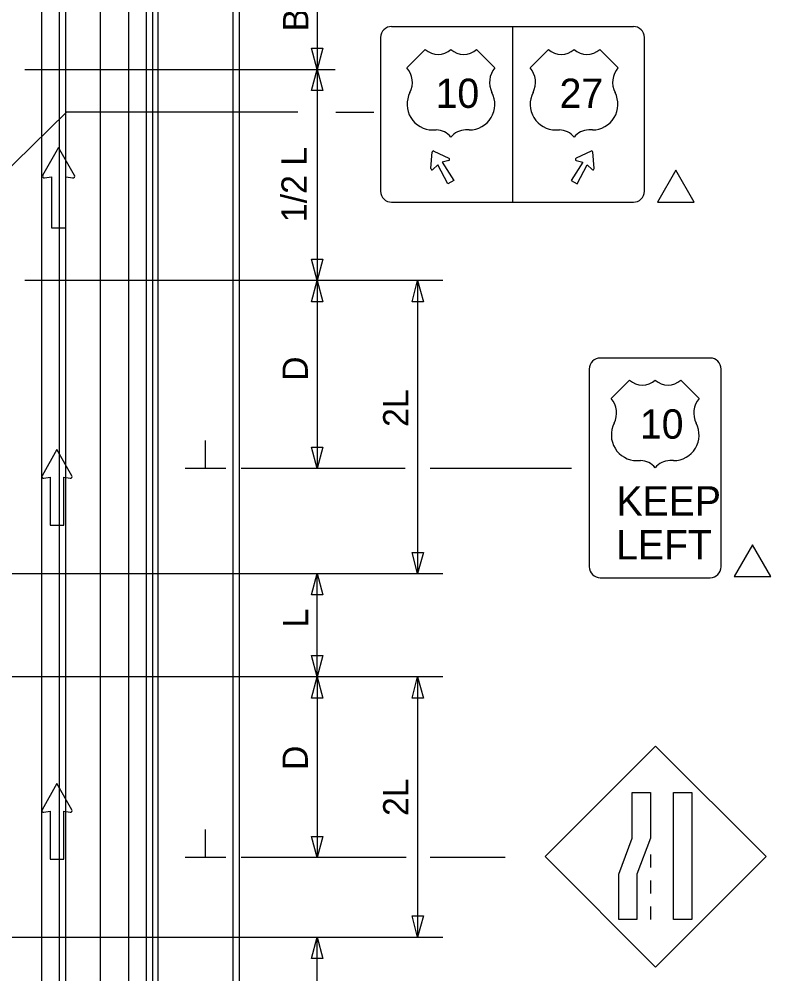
# Model space of a CAD drawing. Extents: x 16604 to 19504, y 6997 to 8305.
# Drawn here: x 16989.3 to 17197.2, y 7467.1 to 7731.2 of the extents above; entities that cross this region are included whole.
import ezdxf

# ---------------------------------------------------------------- set-up
doc = ezdxf.new("R2010")
doc.units = 0
for name, color, linetype in [('ALI_LEGAL_EX', 7, 'Continuous'), ('MT_SCRATCH_LEVEL_E', 7, 'Continuous'), ('PAVT_EDGE_EX', 7, 'Continuous'), ('TRAFFIC_SIGNS_PR', 7, 'Continuous'), ('TYPICAL_EX', 7, 'Continuous'), ('TYPICAL_TEXT_DIMEN_PR', 7, 'Continuous')]:
    doc.layers.add(name, color=color, linetype=linetype)

msp = doc.modelspace()

# ---------------------------------------------------------------- linework, layer by layer
at = {"layer": 'ALI_LEGAL_EX'}
for p, q in [((16995.53, 8241.3), (16995.53, 7423.16)), ((17019.53, 8241.3), (17019.53, 7423.16)), ((17000.51, 7366.28), (17000.51, 7976.48)), ((17024.51, 7366.28), (17024.51, 7976.48)), ((17048.51, 7366.28), (17048.51, 7976.48)), ((17002.26, 7363.06), (17002.26, 7973.25)), ((17026.26, 7363.06), (17026.26, 7973.25)), ((17050.26, 7363.06), (17050.26, 7973.25))]:
    msp.add_line(p, q, dxfattribs=at)
at = {"layer": 'MT_SCRATCH_LEVEL_E'}
for p, q in [((16999.78, 7612.12), (16995.67, 7604.88)), ((17003.93, 7604.88), (16999.78, 7612.12)), ((16996.15, 7604.2), (16997.93, 7604.51)), ((16997.93, 7604.51), (16997.93, 7591.26)), ((17001.67, 7591.26), (17001.67, 7604.51)), ((17001.67, 7604.51), (17003.45, 7604.2)), ((16997.93, 7591.26), (17001.67, 7591.26)), ((16999.78, 7519.75), (16995.67, 7512.51)), ((17003.93, 7512.51), (16999.78, 7519.75)), ((16996.15, 7511.82), (16997.93, 7512.14)), ((16997.93, 7512.14), (16997.93, 7498.88)), ((17001.67, 7498.88), (17001.67, 7512.14)), ((17001.67, 7512.14), (17003.45, 7511.82)), ((16997.93, 7498.88), (17001.67, 7498.88))]:
    msp.add_line(p, q, dxfattribs=at)
for centre, start, end in [((16996.08, 7604.66), 150.4248, 279.9638), ((17003.52, 7604.66), 260.0362, 29.7731), ((16996.08, 7512.28), 150.4248, 279.9638), ((17003.52, 7512.29), 260.0362, 29.7731)]:
    msp.add_arc(centre, 0.463, start, end, dxfattribs=at)
at = {"layer": 'PAVT_EDGE_EX'}
for p, q in [((17011.73, 7751.28), (17011.73, 7396.71)), ((17027.73, 7751.28), (17027.73, 7396.71))]:
    msp.add_line(p, q, dxfattribs=at)
at = {"layer": 'TRAFFIC_SIGNS_PR'}
for p, q in [((17092.34, 7729.14), (17159.17, 7729.14)), ((17125.75, 7729.14), (17125.75, 7680.54)), ((17089.3, 7726.11), (17089.3, 7683.58)), ((17162.2, 7726.11), (17162.2, 7683.58)), ((17103.2, 7689.85), (17103.56, 7694.43)), ((17104.03, 7694.7), (17108.18, 7692.72)), ((17147.48, 7694.7), (17143.33, 7692.72)), ((17148.31, 7689.85), (17147.95, 7694.43)), ((17092.34, 7680.54), (17159.17, 7680.54)), ((17180.4, 7637.43), (17150.03, 7637.43)), ((17146.99, 7634.39), (17146.99, 7579.72)), ((17183.44, 7579.72), (17183.44, 7634.39)), ((17150.03, 7576.68), (17180.4, 7576.68)), ((17165.33, 7530.12), (17134.78, 7499.57)), ((17195.88, 7499.57), (17165.33, 7530.12)), ((17163.93, 7500.12), (17163.93, 7496.52)), ((17134.78, 7499.57), (17165.33, 7469.02)), ((17165.33, 7469.02), (17195.88, 7499.57)), ((17163.93, 7492.92), (17163.93, 7489.32)), ((17163.93, 7485.72), (17163.93, 7482.12))]:
    msp.add_line(p, q, dxfattribs=at)
for points in [[(17108.13, 7692.11), (17106.34, 7691.61), (17109.53, 7686.58), (17107.85, 7685.61), (17105.07, 7690.88), (17103.76, 7689.59)], [(17143.38, 7692.11), (17145.17, 7691.61), (17141.98, 7686.58), (17143.66, 7685.61), (17146.43, 7690.88), (17147.75, 7689.59)]]:
    msp.add_lwpolyline(points, dxfattribs=at)
for points in [[(17163.93, 7517.27), (17163.93, 7504.69), (17160.17, 7494.7), (17160.17, 7482.12), (17155.11, 7482.12), (17155.11, 7494.7), (17158.87, 7504.69), (17158.87, 7517.27)], [(17175.33, 7517.27), (17175.33, 7482.12), (17170.28, 7482.12), (17170.28, 7517.27)]]:
    msp.add_lwpolyline(points, close=True, dxfattribs=at)
for centre, radius, start, end in [((17092.34, 7726.11), 3.04, 90, 180), ((17092.34, 7726.11), 3.04, 90, 180), ((17159.17, 7726.11), 3.04, 0, 90), ((17103.89, 7694.4), 0.329, 64.4823, 175.5177), ((17108.04, 7692.42), 0.329, 285.9885, 64.4823), ((17143.47, 7692.42), 0.329, 115.5177, 254.0115), ((17147.62, 7694.4), 0.329, 4.4823, 115.5177), ((17103.53, 7689.82), 0.329, 175.5177, 314.0115), ((17147.98, 7689.82), 0.329, 225.9885, 4.4823), ((17092.34, 7683.58), 3.04, 180, 270), ((17159.17, 7683.58), 3.04, 270, 0), ((17150.03, 7634.39), 3.04, 90, 180), ((17180.4, 7634.39), 3.04, 0, 90), ((17150.03, 7579.72), 3.04, 180, 270), ((17180.4, 7579.72), 3.04, 270, 0)]:
    msp.add_arc(centre, radius, start, end, dxfattribs=at)
at = {"layer": 'TYPICAL_EX'}
for p, q in [((17096.58, 7717.75), (17101.64, 7722.82)), ((17120.88, 7717.75), (17115.82, 7722.82)), ((17130.63, 7717.75), (17135.69, 7722.82)), ((17154.93, 7717.75), (17149.86, 7722.82)), ((17103.66, 7700.53), (17104.67, 7700.53)), ((17113.8, 7700.53), (17112.79, 7700.53)), ((17137.71, 7700.53), (17138.72, 7700.53)), ((17147.85, 7700.53), (17146.83, 7700.53)), ((17153.06, 7626.29), (17158.13, 7631.36)), ((17177.37, 7626.29), (17172.3, 7631.36)), ((17160.15, 7609.07), (17161.16, 7609.07)), ((17170.29, 7609.07), (17169.27, 7609.07))]:
    msp.add_line(p, q, dxfattribs=at)
for centre, radius, start, end in [((17105.19, 7726.5), 5.11, 226.1404, 313.8596), ((17112.28, 7726.5), 5.11, 226.1404, 313.8596), ((17139.23, 7726.5), 5.11, 226.1404, 313.8596), ((17146.32, 7726.5), 5.11, 226.1404, 313.8596), ((17091.78, 7713.7), 6.28, 333.0977, 40.1936), ((17125.68, 7713.7), 6.28, 139.8064, 206.9023), ((17125.83, 7713.7), 6.28, 333.0977, 40.1936), ((17159.72, 7713.7), 6.28, 139.8064, 206.9023), ((17103.68, 7707.61), 7.08, 152.6698, 269.9013), ((17113.79, 7707.61), 7.08, 270.0987, 27.3302), ((17137.72, 7707.61), 7.08, 152.6698, 269.9013), ((17147.83, 7707.61), 7.08, 270.0987, 27.3302), ((17104.69, 7695.46), 5.07, 37.1038, 90.1385), ((17112.78, 7695.46), 5.07, 89.8615, 142.8962), ((17138.73, 7695.46), 5.07, 37.1038, 90.1385), ((17146.82, 7695.46), 5.07, 89.8615, 142.8962), ((17161.67, 7635.04), 5.11, 226.1404, 313.8596), ((17168.76, 7635.04), 5.11, 226.1404, 313.8596), ((17148.27, 7622.24), 6.28, 333.0977, 40.1936), ((17182.16, 7622.24), 6.28, 139.8064, 206.9023), ((17160.16, 7616.15), 7.08, 152.6698, 269.9013), ((17170.27, 7616.15), 7.08, 270.0987, 27.3302), ((17161.17, 7604), 5.07, 37.1038, 90.1385), ((17169.26, 7604), 5.07, 89.8615, 142.8962)]:
    msp.add_arc(centre, radius, start, end, dxfattribs=at)
at = {"layer": 'TYPICAL_TEXT_DIMEN_PR'}
for p, q in [((17071.73, 7739.84), (17071.73, 7717.28)), ((17071.73, 7717.28), (17070.16, 7723.15)), ((17070.16, 7723.15), (17071.73, 7723.15)), ((17071.73, 7723.15), (17073.3, 7723.15)), ((17073.3, 7723.15), (17071.73, 7717.28)), ((16990.92, 7717.28), (17076.73, 7717.28)), ((17070.16, 7711.42), (17071.73, 7717.28)), ((17071.73, 7717.28), (17071.73, 7658.89)), ((17071.73, 7717.28), (17073.3, 7711.42)), ((17071.73, 7711.42), (17070.16, 7711.42)), ((17073.3, 7711.42), (17071.73, 7711.42)), ((17002.42, 7705.43), (16982.68, 7686.16)), ((17066.41, 7705.43), (17002.42, 7705.43)), ((17076.92, 7705.43), (17087.42, 7705.43)), ((17000.23, 7695.69), (16995.84, 7687.97)), ((17004.65, 7687.97), (17000.23, 7695.69)), ((16996.36, 7687.24), (16998.25, 7687.58)), ((16998.25, 7687.58), (16998.25, 7673.44)), ((17002.24, 7673.44), (17002.24, 7687.58)), ((17002.24, 7687.58), (17004.14, 7687.24)), ((16998.25, 7673.44), (17002.24, 7673.44)), ((17071.73, 7658.89), (17070.16, 7664.75)), ((17070.16, 7664.75), (17071.73, 7664.75)), ((17071.73, 7664.75), (17073.3, 7664.75)), ((17073.3, 7664.75), (17071.73, 7658.89)), ((17106.52, 7658.89), (16990.92, 7658.89)), ((17070.16, 7653.03), (17071.73, 7658.89)), ((17071.73, 7658.89), (17073.3, 7653.03)), ((17071.73, 7658.89), (17071.73, 7606.89)), ((17097.97, 7653.03), (17099.53, 7658.89)), ((17099.53, 7658.89), (17099.53, 7577.83)), ((17099.53, 7658.89), (17101.1, 7653.03)), ((17071.73, 7653.03), (17070.16, 7653.03)), ((17073.3, 7653.03), (17071.73, 7653.03)), ((17099.53, 7653.03), (17097.97, 7653.03)), ((17101.1, 7653.03), (17099.53, 7653.03)), ((17040.85, 7606.89), (17040.85, 7614.67)), ((17071.73, 7606.89), (17070.16, 7612.75)), ((17070.16, 7612.75), (17071.73, 7612.75)), ((17071.73, 7612.75), (17073.3, 7612.75)), ((17073.3, 7612.75), (17071.73, 7606.89)), ((17046.48, 7606.89), (17035.23, 7606.89)), ((17096.09, 7606.89), (17050.73, 7606.89)), ((17142.09, 7606.89), (17103.01, 7606.89)), ((17099.53, 7577.83), (17097.97, 7583.7)), ((17097.97, 7583.7), (17099.53, 7583.7)), ((17099.53, 7583.7), (17101.1, 7583.7)), ((17101.1, 7583.7), (17099.53, 7577.83)), ((16966.78, 7577.83), (17106.52, 7577.83)), ((17070.16, 7571.97), (17071.73, 7577.83)), ((17071.73, 7549.27), (17071.73, 7577.83)), ((17071.73, 7577.83), (17073.3, 7571.97)), ((17071.73, 7571.97), (17070.16, 7571.97)), ((17073.3, 7571.97), (17071.73, 7571.97)), ((17071.73, 7549.27), (17070.16, 7555.13)), ((17070.16, 7555.13), (17071.73, 7555.13)), ((17071.73, 7555.13), (17073.3, 7555.13)), ((17073.3, 7555.13), (17071.73, 7549.27)), ((17106.52, 7549.27), (16945.23, 7549.27)), ((17070.16, 7543.41), (17071.73, 7549.27)), ((17071.73, 7549.27), (17071.73, 7499.27)), ((17071.73, 7549.27), (17073.3, 7543.41)), ((17097.97, 7543.41), (17099.53, 7549.27)), ((17099.53, 7549.27), (17101.1, 7543.41)), ((17099.53, 7549.27), (17099.53, 7477.27)), ((17071.73, 7543.41), (17070.16, 7543.41)), ((17073.3, 7543.41), (17071.73, 7543.41)), ((17099.53, 7543.41), (17097.97, 7543.41)), ((17101.1, 7543.41), (17099.53, 7543.41)), ((17040.85, 7499.27), (17040.85, 7507.06)), ((17071.73, 7499.27), (17070.16, 7505.13)), ((17070.16, 7505.13), (17071.73, 7505.13)), ((17071.73, 7505.13), (17073.3, 7505.13)), ((17073.3, 7505.13), (17071.73, 7499.27)), ((17046.48, 7499.27), (17035.23, 7499.27)), ((17096.32, 7499.27), (17050.73, 7499.27)), ((17123.74, 7499.27), (17103.01, 7499.27)), ((17099.53, 7477.27), (17097.97, 7483.13)), ((17097.97, 7483.13), (17099.53, 7483.13)), ((17099.53, 7483.13), (17101.1, 7483.13)), ((17101.1, 7483.13), (17099.53, 7477.27)), ((16945.23, 7477.27), (17106.52, 7477.27)), ((17070.16, 7471.41), (17071.73, 7477.27)), ((17071.73, 7446.71), (17071.73, 7477.27)), ((17071.73, 7477.27), (17073.3, 7471.41)), ((17071.73, 7471.41), (17070.16, 7471.41)), ((17073.3, 7471.41), (17071.73, 7471.41))]:
    msp.add_line(p, q, dxfattribs=at)
for points in [[(17170.92, 7689.36), (17165.83, 7680.54), (17176.01, 7680.54)], [(17192.11, 7585.81), (17187.02, 7576.99), (17197.2, 7576.99)]]:
    msp.add_lwpolyline(points, close=True, dxfattribs=at)
for centre, start, end in [((16996.28, 7687.73), 150.4248, 279.9638), ((17004.21, 7687.73), 260.0362, 29.7731)]:
    msp.add_arc(centre, 0.494, start, end, dxfattribs=at)

# ---------------------------------------------------------------- texts
at = {"layer": 'TRAFFIC_SIGNS_PR'}
for s, p in [('10', (17104.5, 7706.62)), ('27', (17138.77, 7706.62)), ('10', (17160.99, 7615.15)), ('KEEP', (17154.5, 7593.89)), ('LEFT', (17154.39, 7581.74))]:
    msp.add_text(s, height=8.1, dxfattribs=at).set_placement(p)
at = {"layer": 'TYPICAL_TEXT_DIMEN_PR'}
for s, p in [('B', (17069.29, 7727.79)), ('1/2 L', (17068.87, 7675.03)), ('D', (17069.17, 7631.11)), ('2L', (17096.98, 7618.39)), ('L', (17069.26, 7562.91)), ('D', (17069.17, 7523.49)), ('2L', (17096.98, 7510.77))]:
    msp.add_text(s, height=7, rotation=90, dxfattribs=at).set_placement(p)

doc.saveas('drawing.dxf')
